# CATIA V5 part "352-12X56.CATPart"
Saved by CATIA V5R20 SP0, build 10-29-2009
Part number: 352-12X56
Definition: NONE
Nomenclature: 352-12X56
Source: Unknown
Description: 352-12X56
Bounding box of the stored display mesh (mm): x 0 to 56, y -9 to 9, z -9 to 9
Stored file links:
  C:\Users\Utente\Desktop\IO LAVORO\3D X SITO CF\X SITO\PLASTICA\352\352-12X56.CATPart
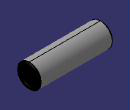
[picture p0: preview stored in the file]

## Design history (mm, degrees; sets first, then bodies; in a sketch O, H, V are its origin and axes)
Body1 "352-12X56" (main body)
  Solid1: solid without history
